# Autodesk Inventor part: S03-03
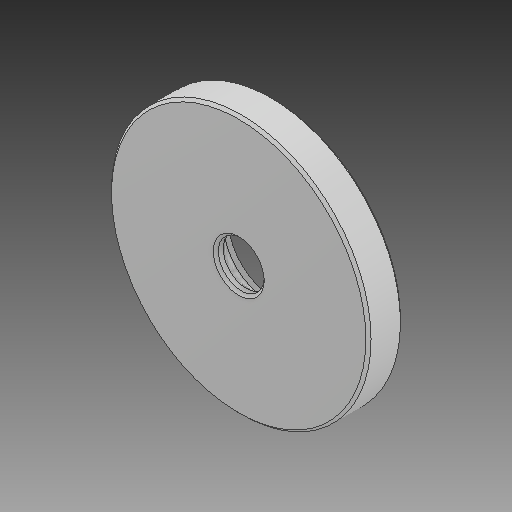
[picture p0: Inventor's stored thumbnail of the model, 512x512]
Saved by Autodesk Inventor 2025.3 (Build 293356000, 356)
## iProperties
Created: 2025-04
Part Number: S03-03
Material: Všeobecné
Document SubType Name: Modeling
Designer: Patrik
Density: 1 g/cm^3
Appearance: Výchozí
Description: Dorazová destička pro vyhazovací paket
Stock Number: E 1500/30x 4
User Status: 1.7131
Author: Patrik
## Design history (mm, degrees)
feature "Base1"
node "Těleso1"
